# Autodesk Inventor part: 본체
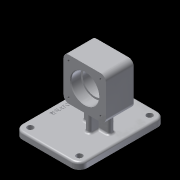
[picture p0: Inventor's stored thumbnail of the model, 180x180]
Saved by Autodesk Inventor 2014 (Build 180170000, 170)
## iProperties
Created: 2020-11
Part Number: 본체
Material: 알루미늄 6061
Document SubType Name: Modeling
Designer: kh
Density: 2.71 g/cm^3
Appearance: 알루미늄 - 평지
Mass: 670.16 g
Surface Area: 537.618 cm^2
Volume: 247.291 cm^3
Author: kh
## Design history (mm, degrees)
sketch "스케치1"
  geometry: L1 (-65, -49)-(65, -49); L2 (65, -49)-(65, 49); L3 (65, 49)-(-65, 49); L4 (-65, 49)-(-65, -49); L5 (-65, -49)-(65, 49); L6 (65, -49)-(-65, 49); 1 further point
  constraints: 12 end point, 2 midpoint, 2 parallel, 1 horizontal, 1 perpendicular
  dimensions: "d0" = 130 distance of L2.end L3.end; "d1" = 98 distance of L1.end L2.end
extrude "돌출1" new body sketch "스케치1" distance "d2" = 10; taper "d3" = 0 deg
node "작업 평면1"
node "작업 평면4"
sketch "스케치11"
  geometry: L1 (44, 92)-(86, 92); L2 (86, 92)-(86, 28); L3 (86, 28)-(44, 28); L4 (44, 28)-(44, 92); L5 (44, 92)-(86, 28); L6 (86, 92)-(44, 28); L7 (0, -10)-(130, -10) reference; 3 further points
  constraints: 12 end point, 3 midpoint, 2 parallel, 1 horizontal, 1 perpendicular, 1 vertical alignment
  dimensions: "d34" = 64 distance of L1.end L2.end; "d35" = 42 distance of L1.start L1.end; "d36" = 70 distance from line of L7 point (65, 60)
extrude "돌출5" join sketch "스케치11" stored distance "d37" = 64; taper "d38" = 0 deg
sketch "스케치12"
  geometry: L1 (0, 64)-(0, 0) reference; L2 (38, 94)-(38, -4) reference; 3 further points
  constraints: 1 horizontal alignment, 1 midpoint
  dimensions: "d39" = 70 distance from line of L2 point (-32, 32)
hole "구멍2" sketch "스케치12" at (-32, 32) diameter "d40" = 36; stored, may be unused: countersink angle "d44" = 90 deg, drill point angle "d46" = 118 deg; dims "d41" = 6, "d42" = 42, "d43" = 15, "d45" = 8
hole "구멍3" diameter "d49" = 42; stored, may be unused: countersink angle "d53" = 90 deg, drill point angle "d55" = 0 deg; dims "d50" = 6, "d51" = 42, "d52" = 15, "d54" = 15, "d102" = 10, "d103" = 10
sketch "스케치13"
  geometry: L1 (-8, 56)-(-56, 56); L2 (-56, 56)-(-56, 8); L3 (-56, 8)-(-8, 8); L4 (-8, 8)-(-8, 56); L5 (-8, 56)-(-56, 8); L6 (-56, 56)-(-8, 8); C1 r 21 at (-32, 32) reference; 5 further points
  constraints: 12 end point, 4 coincident, 2 midpoint, 2 parallel, 1 horizontal, 1 perpendicular
  dimensions: "d56" = 48 distance of L1.end L2.end; "d57" = 48 distance of L2.end L3.end
hole "구멍4" sketch "스케치13" at (-56, 8), (-56, 56), (-8, 8), (-8, 56) diameter "d58" = 3.242; stored, may be unused: countersink angle "d62" = 90 deg, drill point angle "d64" = 118 deg; dims "d59" = 8, "d60" = 42, "d61" = 15, "d63" = 10
fillet "모깎기1" dims "d65" = 12
sketch "스케치14"
  geometry: L1 (7, 3.823)-(-33, 3.823); L2 (-33, 3.823)-(-33, -35.343); L3 (-33, -35.343)-(7, -35.343); L4 (7, -35.343)-(7, 3.823); L5 (19, -28)-(-45, -28) reference; 3 further points
  constraints: 8 end point, 2 midpoint, 2 parallel, 1 horizontal, 1 perpendicular, 1 vertical alignment
  dimensions: "d66" = 40 distance between parallel lines of L4 L2
extrude "돌출6" join sketch "스케치14" stored distance "d67" = 8; taper "d68" = 0 deg
sketch "스케치15"
  geometry: L1 (48, 33.076)-(48, -3.327); L2 (0, -10)-(0, 0) reference; 1 further point
  constraints: 2 end point, 1 vertical
  dimensions: "d70" = 17 distance from line of point (65, 0) L1
feature "리브1" sketch "스케치15" dims "d71" = 1, "d72" = 8, "d73" = 0, "d74" = 0, "d75" = 1, "d76" = 1
hole "구멍5" diameter "d79" = 9; stored, may be unused: countersink angle "d83" = 90 deg, drill point angle "d85" = 118 deg; dims "d77" = 10, "d78" = 10, "d80" = 8, "d81" = 42, "d82" = 15, "d84" = 10
fillet "모깎기2" dims "d90" = 0.3
fillet "모깎기3" dims "d91" = 3
fillet "모깎기4" dims "d92" = 3
fillet "모깎기5" dims "d93" = 8
fillet "모깎기6" dims "d94" = 3
chamfer "모따기1" distance "d95" = 1; stored, may be unused: second distance "d96" = 2, angle "d97" = 45 deg
sketch "스케치16"
  geometry: L1 (53, 49)-(-53, 49) reference; L2 (65, -37)-(65, 37) reference; 2 further points
  constraints: 1 other
  dimensions: "d98" = 10 distance from line of point (0, 39) L1; "d99" = 65 distance from line of L2 point (0, 39)
feature "엠보싱1" sketch "스케치16" dims "d0" = 130, "d1" = 98, "d100" = 0.5, "d101" = 0
node "솔리드1"
mirror "대칭1"
mirror "대칭2"
pattern_linear "직사각형 패턴1"
pattern_linear "직사각형 패턴2"
other parameters: "d12" = -62, "d33" = -62
